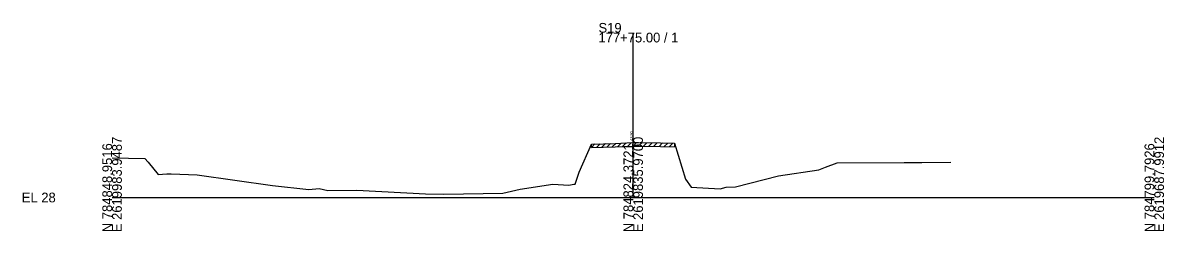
# Model space of a CAD drawing. Extents: x -26 to 1603, y -10 to 5028.
# Drawn here: x 1274.3 to 1602.9, y 490.3 to 550.3 of the extents above; entities that cross this region are included whole.
import ezdxf

# ---------------------------------------------------------------- set-up
doc = ezdxf.new("R2010")
doc.units = 0
for name, color, linetype in [('RD_GPK_XS_Cell', 7, 'Continuous'), ('RD_XS_ExGround', 7, 'Continuous'), ('RD_XS_ExPaveRet', 7, 'Continuous'), ('RD_XS_TX_Elev_EX', 7, 'Continuous')]:
    doc.layers.add(name, color=color, linetype=linetype)

msp = doc.modelspace()

# ---------------------------------------------------------------- linework, layer by layer
at = {"layer": 'RD_GPK_XS_Cell'}
for p, q in [((1450.01, 500), (1450.01, 547.42)), ((1300, 500), (1450.01, 500)), ((1450.01, 500), (1600.01, 500))]:
    msp.add_line(p, q, dxfattribs=at)
at = {"layer": 'RD_XS_ExGround'}
for p, q in [((1434.46, 507.33), (1437.96, 515.38)), ((1437.96, 515.38), (1444.8, 515.57)), ((1444.8, 515.57), (1449.89, 515.81)), ((1449.89, 515.81), (1451.51, 515.78)), ((1451.51, 515.78), (1457.82, 515.71)), ((1457.82, 515.71), (1461.88, 515.62)), ((1461.88, 515.62), (1465.08, 505.24)), ((1300, 511.38), (1309.42, 511.24)), ((1309.42, 511.24), (1310.4, 510.13)), ((1310.4, 510.13), (1313.29, 506.58)), ((1505.33, 508.77), (1508.72, 509.98)), ((1508.72, 509.98), (1527.97, 510.1)), ((1527.97, 510.1), (1530.96, 510.11)), ((1530.96, 510.11), (1533.09, 510.09)), ((1533.09, 510.09), (1541.46, 510.2)), ((1313.29, 506.58), (1315.78, 506.81)), ((1315.78, 506.81), (1317.04, 506.76)), ((1317.04, 506.76), (1324.53, 506.49)), ((1324.53, 506.49), (1346.21, 503.42)), ((1433.28, 503.87), (1434.46, 507.33)), ((1479.43, 503.1), (1491.86, 506.23)), ((1491.86, 506.23), (1503.43, 507.99)), ((1503.43, 507.99), (1505.33, 508.77)), ((1346.21, 503.42), (1356.66, 502.34)), ((1417.44, 502.38), (1426.89, 503.79)), ((1426.89, 503.79), (1431.52, 503.57)), ((1431.52, 503.57), (1432.93, 503.84)), ((1432.93, 503.84), (1433.28, 503.87)), ((1465.08, 505.24), (1466.7, 503.01)), ((1466.7, 503.01), (1475.05, 502.53)), ((1475.05, 502.53), (1476.8, 502.93)), ((1476.8, 502.93), (1479.43, 503.1)), ((1356.66, 502.34), (1359.58, 502.6)), ((1359.58, 502.6), (1362.12, 502.02)), ((1362.12, 502.02), (1370.46, 502.13)), ((1370.46, 502.13), (1390.19, 501.03)), ((1390.19, 501.03), (1395.45, 500.97)), ((1395.45, 500.97), (1412.45, 501.29)), ((1412.45, 501.29), (1417.44, 502.38))]:
    msp.add_line(p, q, dxfattribs=at)
at = {"layer": 'RD_XS_ExPaveRet'}
for p, q in [((1437.96, 514.38), (1438.99, 515.41)), ((1437.96, 514.38), (1437.96, 515.38)), ((1437.96, 514.38), (1444.8, 514.57)), ((1439.46, 514.42), (1440.49, 515.45)), ((1440.96, 514.46), (1441.99, 515.49)), ((1442.46, 514.51), (1443.49, 515.53)), ((1443.96, 514.55), (1445, 515.58)), ((1444.8, 514.57), (1449.89, 514.81)), ((1445.46, 514.6), (1446.51, 515.65)), ((1446.96, 514.67), (1448.01, 515.72)), ((1448.46, 514.74), (1449.51, 515.79)), ((1449.89, 514.81), (1451.51, 514.78)), ((1449.96, 514.8), (1450.95, 515.79)), ((1451.46, 514.78), (1452.45, 515.77)), ((1451.51, 514.78), (1457.82, 514.71)), ((1452.96, 514.76), (1453.95, 515.75)), ((1454.46, 514.74), (1455.45, 515.73)), ((1455.96, 514.73), (1456.95, 515.72)), ((1457.46, 514.71), (1458.45, 515.69)), ((1457.82, 514.71), (1461.88, 514.62)), ((1458.96, 514.68), (1459.94, 515.66)), ((1460.46, 514.65), (1461.44, 515.63)), ((1461.88, 515.62), (1461.88, 514.62))]:
    msp.add_line(p, q, dxfattribs=at)

# ---------------------------------------------------------------- texts
at = {"layer": 'RD_GPK_XS_Cell'}
for s, p in [('S19', (1440.01, 547.42)), ('177+75.00 / 1', (1440.01, 544.62)), ('EL 28', (1274, 498.6))]:
    msp.add_text(s, height=2.8, dxfattribs=at).set_placement(p)
for s, p in [('E 2619983.9487', (1302.8, 490)), ('E 2619835.9700', (1452.81, 490)), ('E 2619687.9912', (1602.81, 490)), ('N 784848.9516', (1300, 490)), ('N 784824.3721', (1450.01, 490)), ('N 784799.7926', (1600.01, 490))]:
    msp.add_text(s, height=2.8, rotation=90, dxfattribs=at).set_placement(p)
at = {"layer": 'RD_XS_TX_Elev_EX'}
msp.add_text('43.80', height=0.8, rotation=90, dxfattribs=at).set_placement((1449.91, 516.3))

doc.saveas('drawing.dxf')
